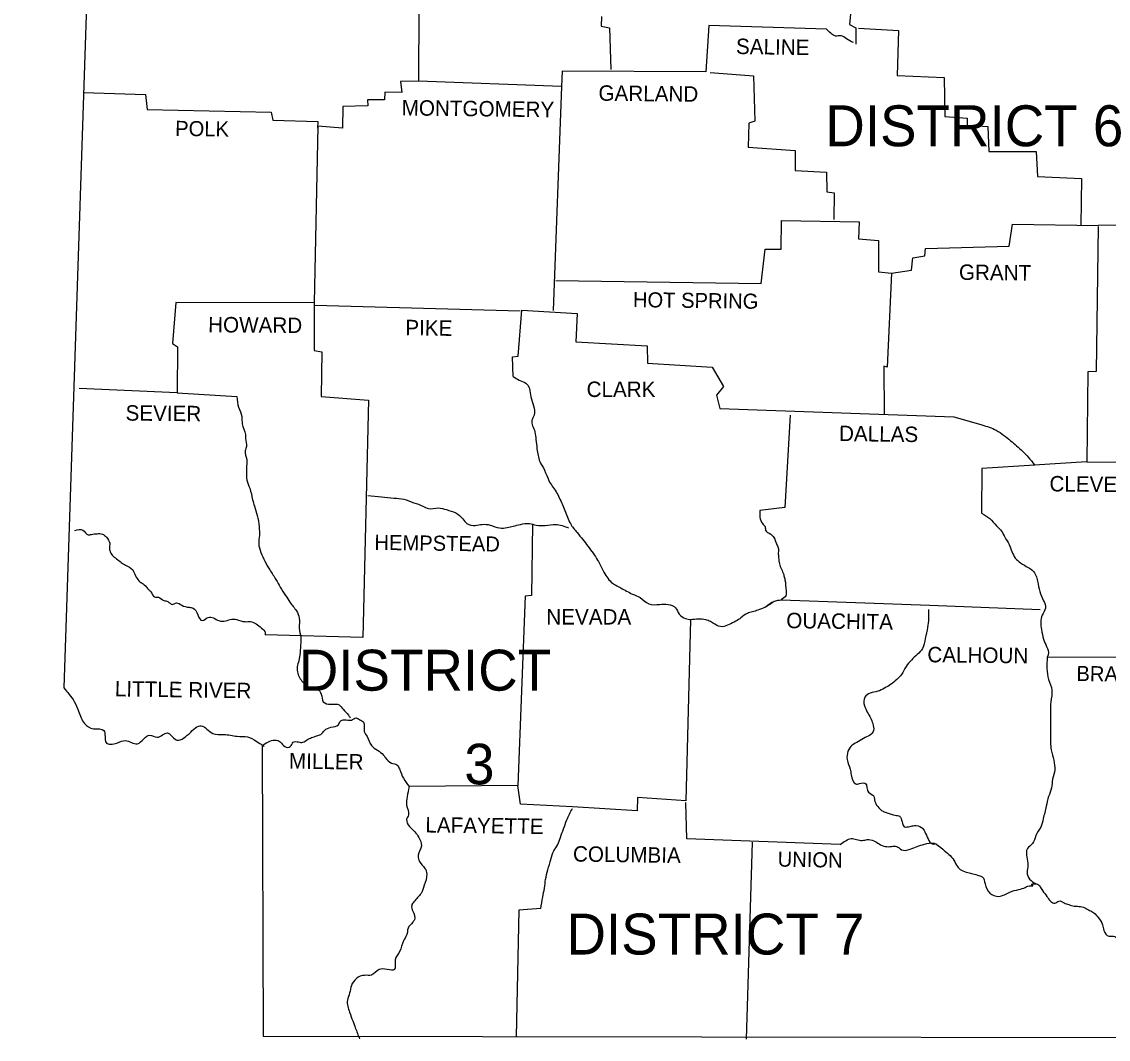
# Model space of a CAD drawing. Extents: x -712 to 3943, y 73 to 2823.
# Drawn here: x 2703.7 to 2999.8, y 1432.6 to 1709.8 of the extents above; entities that cross this region are included whole.
import ezdxf

# ---------------------------------------------------------------- set-up
doc = ezdxf.new("R2010")
doc.units = 0
for name, color, linetype in [('1', 7, 'Continuous'), ('2', 7, 'Continuous'), ('3', 7, 'Continuous')]:
    doc.layers.add(name, color=color, linetype=linetype)

msp = doc.modelspace()

# ---------------------------------------------------------------- linework, layer by layer
at = {"layer": '1'}
for points in [[(2703.71, 1956.42), (2723.96, 1793.81), (2715.15, 1528.37)], [(2811.96, 1733.39), (2811.82, 1693.62), (2806.93, 1693.52), (2807.32, 1690.59), (2802.62, 1690.68), (2802.53, 1688.53), (2797.93, 1688.53), (2798.03, 1686.97), (2791.18, 1686.77), (2791.08, 1680.8), (2784.43, 1681.39), (2783.35, 1633.25), (2745.68, 1633.35), (2744.8, 1622.19), (2746.17, 1621.22), (2746.07, 1608.69), (2719.36, 1609.87)], [(2961.91, 1722.77), (2954.86, 1723.56), (2955.16, 1720.92), (2942.34, 1720.43), (2941.95, 1716.61), (2929.91, 1715.93), (2929.23, 1709.08), (2930.99, 1708.2), (2930.99, 1703.7)], [(2922.97, 1707.81), (2890.97, 1708.78), (2890.09, 1696.16), (2850.96, 1696.36), (2850.76, 1692.15)], [(2861.72, 1711.23), (2861.62, 1708.59), (2863.87, 1708.2), (2864.26, 1696.85)], [(2931.68, 1708.1), (2942.63, 1707.41), (2942.24, 1695.18), (2955.06, 1694.69), (2955.26, 1684.03), (2961.32, 1683.54), (2961.32, 1681.68), (2967, 1681.29), (2967.19, 1674.44), (2980.11, 1674.44), (2980.5, 1667.69), (2992.44, 1667.1), (2992.34, 1654.38)], [(2850.76, 1692.15), (2811.82, 1693.62)], [(2891.27, 1695.97), (2903.11, 1695.09), (2903.5, 1682.76), (2901.83, 1682.17), (2901.64, 1675.62), (2914.46, 1674.74), (2914.46, 1669.35), (2922.97, 1668.86), (2923.07, 1663.48), (2925.12, 1663.19), (2925.02, 1655.95)], [(2720.54, 1690.59), (2737.46, 1690), (2737.85, 1685.89), (2771.71, 1685.2), (2772.1, 1683.05), (2784.43, 1682.66), (2784.33, 1680.8)], [(2850.76, 1692.15), (2848.51, 1631.2)], [(3109.06, 1665.64), (3072.08, 1666.61), (3071.88, 1654.58), (2997.03, 1654.29)], [(2849.2, 1639.32), (2905.16, 1638.53), (2906.24, 1647.83), (2910.64, 1647.83), (2910.74, 1655.66), (2931.87, 1655.36), (2931.68, 1650.67), (2937.16, 1650.27), (2937.16, 1641.66), (2940.68, 1641.37)], [(2940.68, 1641.37), (2946.16, 1642.15), (2946.55, 1645.48), (2949.78, 1646.07), (2949.97, 1648.02), (2972.77, 1648.71), (2973.65, 1654.68), (2997.03, 1654.29)], [(2997.03, 1654.09), (2996.45, 1614.56), (2994.2, 1614.47), (2993.9, 1589.91)], [(2940.68, 1641.37), (2939.5, 1615.74), (2938.62, 1616.03), (2938.72, 1602.72)], [(2783.35, 1633.25), (2783.35, 1620.24), (2785.5, 1619.85), (2785.31, 1607.71), (2798.22, 1606.74), (2796.66, 1542.06), (2770.04, 1542.75)], [(2783.55, 1632.57), (2839.51, 1631.1)], [(2837.65, 1613.19), (2837.46, 1618.57), (2839.02, 1618.67), (2840, 1631.29), (2855.07, 1630.32), (2854.68, 1622.59), (2874.15, 1621.51), (2874.24, 1616.81), (2891.85, 1615.74), (2894.89, 1610.45), (2893.03, 1608.11), (2893.91, 1604.49), (2957.7, 1602.14)], [(2746.07, 1608.69), (2762.31, 1607.71)], [(2913.09, 1602.63), (2911.62, 1577.48), (2904.87, 1576.7)], [(2993.9, 1589.91), (2979.62, 1589.03)], [(2993.9, 1589.91), (3028.54, 1589.71)], [(2979.81, 1589.03), (2965.33, 1588.15), (2965.24, 1575.92)], [(2842.84, 1572.98), (2842.64, 1553.51), (2840.88, 1553.31), (2838.92, 1501.75)], [(2910.64, 1552.34), (2951.15, 1550.87), (2981.18, 1549.69)], [(2885.98, 1546.86), (2884.71, 1497.55), (2871.5, 1498.43), (2871.41, 1494.81), (2853.79, 1495.88)], [(2983.14, 1536.68), (3027.36, 1536.78)], [(2769.26, 1512.61), (2769.46, 1433.46), (3128.04, 1432.87)], [(2853.79, 1495.88), (2839.61, 1496.67), (2838.92, 1501.75), (2809.28, 1501.46)], [(2926.69, 1485.61), (2884.91, 1487.17), (2884.71, 1497.06)], [(2902.72, 1486.29), (2901.15, 1432.58)], [(2845.18, 1468.19), (2839.12, 1467.8), (2838.43, 1433.36)]]:
    msp.add_lwpolyline(points, dxfattribs=at)
for points in [[(2930.31, 1704.19), (2928.45, 1705.16), (2926.98, 1706.04), (2925.41, 1705.95), (2924.14, 1706.73), (2922.97, 1707.81)], [(2837.65, 1613.19), (2839.22, 1612.21), (2841.08, 1611.33), (2842.05, 1609.87), (2842.45, 1607.62), (2843.13, 1605.17), (2843.33, 1602.63), (2842.74, 1601.26), (2843.52, 1598.13), (2843.82, 1595.97), (2844.11, 1593.43), (2844.89, 1590.01), (2846.16, 1587.66), (2847.34, 1584.82), (2849.29, 1581.79), (2850.96, 1578.46), (2851.74, 1576.7), (2853.21, 1573.08), (2855.07, 1570.63), (2858, 1566.91), (2860.64, 1563.1), (2862.11, 1560.26), (2864.36, 1557.13), (2866.91, 1555.57), (2870.13, 1553.9), (2872.19, 1552.92), (2874.54, 1551.26), (2877.57, 1551.06), (2879.82, 1551.06), (2881.88, 1550.18), (2882.85, 1548.42), (2884.61, 1547.25), (2885.98, 1546.86)], [(2762.31, 1607.71), (2762.8, 1604.78), (2763.68, 1602.24), (2763.78, 1600.28), (2764.66, 1597.34), (2764.66, 1596.27), (2764.96, 1594.11), (2764.56, 1592.94), (2765.05, 1590.59), (2764.96, 1588.83), (2764.96, 1587.36), (2765.05, 1584.92), (2765.84, 1582.76), (2766.62, 1579.54), (2767.11, 1577.87), (2767.89, 1575.33), (2768.38, 1572.2), (2768.48, 1569.85), (2768.28, 1567.7), (2768.87, 1565.25), (2769.95, 1562.81), (2771.32, 1560.46), (2772.98, 1557.82), (2774.15, 1555.76), (2775.62, 1553.51), (2776.79, 1551.65), (2778.56, 1549.3), (2779.34, 1547.35), (2779.34, 1544.61), (2779.73, 1542.06), (2779.63, 1539.23), (2779.44, 1536.68), (2778.75, 1533.16), (2779.24, 1531.5), (2781.1, 1529.05), (2782.27, 1528.37), (2784.33, 1527.97), (2785.31, 1526.6), (2785.89, 1524.55), (2787.95, 1523.86), (2790.2, 1523.67), (2791.27, 1522.49), (2792.74, 1520.93), (2793.23, 1520.15)], [(2957.7, 1602.14), (2965.33, 1599.98), (2969.25, 1598.52), (2973.16, 1595.68), (2976.39, 1592.84), (2979.62, 1589.22)], [(2798.03, 1580.71), (2801.74, 1580.42), (2805.17, 1580.03), (2807.81, 1579.73), (2810.55, 1578.75), (2813, 1577.87), (2814.56, 1577.19), (2817.2, 1577.38), (2819.45, 1576.89), (2822, 1576.01), (2823.86, 1574.35), (2825.03, 1573.08), (2827.28, 1572.59), (2829.14, 1572.88), (2831.39, 1572.69), (2833.93, 1571.9), (2835.99, 1572), (2837.65, 1572.39), (2839.61, 1572.88), (2842.05, 1573.08), (2843.91, 1572.69), (2846.36, 1572.59), (2849.2, 1572.88), (2852.72, 1571.9)], [(2904.87, 1576.7), (2904.87, 1574.84), (2905.55, 1573.08), (2906.24, 1572.3), (2906.53, 1571.02), (2907.41, 1570.44), (2908.68, 1569.26), (2909.37, 1567.6), (2909.86, 1566.52), (2909.86, 1565.15), (2909.96, 1563.78), (2910.15, 1562.12), (2911.33, 1559.19), (2911.62, 1558.01), (2911.81, 1557.03), (2911.91, 1555.37), (2911.91, 1553.41), (2910.64, 1552.34)], [(2965.24, 1575.92), (2967.49, 1574.45), (2969.34, 1572.49), (2970.71, 1571.02), (2971.59, 1569.36), (2972.77, 1567.4), (2974.43, 1563.69), (2975.9, 1562.41), (2977.95, 1561.14), (2979.23, 1560.26), (2980.5, 1557.42), (2981.09, 1554.59), (2982.16, 1552.04), (2982.65, 1550.09), (2981.77, 1548.13), (2981.57, 1544.22), (2982.16, 1541.57), (2982.94, 1539.62), (2983.43, 1537.37), (2983.14, 1536.68)], [(2718.19, 1571.22), (2720.34, 1571.32), (2721.81, 1570.05), (2722.69, 1570.14), (2724.25, 1570.34), (2725.72, 1570.24), (2726.8, 1569.36), (2727.68, 1567.8), (2727.58, 1566.33), (2727.68, 1565.74), (2728.36, 1564.47), (2729.54, 1563.49), (2730.81, 1562.51), (2731.98, 1561.73), (2733.94, 1560.46), (2734.14, 1560.07), (2734.92, 1558.5), (2735.9, 1557.23), (2737.07, 1556.45), (2738.34, 1555.08), (2738.93, 1554.49), (2739.91, 1553.12), (2740.98, 1553.02), (2742.45, 1552.14), (2743.53, 1551.85), (2744.7, 1551.06), (2745.88, 1551.46), (2747.34, 1550.87), (2749.3, 1550.28), (2750.38, 1550.09), (2751.65, 1548.23), (2752.92, 1546.66), (2754.49, 1547.54), (2757.42, 1546.66), (2759.28, 1546.56), (2760.94, 1547.05), (2762.22, 1546.96), (2764.56, 1546.37), (2766.03, 1546.37), (2767.6, 1545.78), (2769.06, 1544.61), (2770.04, 1543.34), (2770.04, 1542.75)], [(2908.78, 1551.95), (2906.24, 1550.28), (2904.28, 1549.5), (2902.81, 1549.01), (2901.44, 1548.62), (2899.68, 1547.44), (2898.31, 1546.47), (2896.45, 1545.59), (2894.69, 1545), (2892.54, 1545.68), (2891.37, 1546.37), (2890.09, 1546.86), (2885.98, 1546.86)], [(2906.24, 1550.28), (2908.78, 1551.95), (2910.64, 1552.34)], [(2950.75, 1549.69), (2950.56, 1544.8), (2949.87, 1541.77), (2949.19, 1539.03), (2947.72, 1537.46), (2946.16, 1535.9), (2944.69, 1534.14), (2943.42, 1531.99), (2942.14, 1530.62), (2940.48, 1529.25), (2938.82, 1528.27), (2936.96, 1527.39), (2934.9, 1526.9), (2933.44, 1525.82), (2933.34, 1523.47), (2935, 1520.15), (2935.59, 1518.58), (2935.79, 1516.72), (2935.1, 1515.65), (2933.53, 1514.77), (2931.68, 1513.69), (2930.01, 1512.71), (2928.84, 1511.05), (2928.64, 1508.8), (2929.43, 1506.16), (2929.72, 1504.59), (2930.99, 1502.14), (2931.97, 1502.24), (2933.73, 1502.14), (2933.93, 1501.65), (2934.02, 1501.17), (2934.42, 1499.89), (2935.88, 1498.82), (2936.08, 1497.84), (2936.96, 1495.98), (2938.43, 1494.71), (2939.5, 1494.32), (2941.75, 1493.63), (2942.93, 1493.34), (2944.2, 1490.5), (2945.77, 1490.6), (2946.94, 1490.79), (2948.9, 1490.31), (2949.78, 1489.13), (2950.66, 1487.17), (2951.83, 1485.8), (2952.61, 1485.8)], [(2983.14, 1536.68), (2983.53, 1530.62), (2984.41, 1527.68), (2984.12, 1524.55), (2984.02, 1521.52), (2984.02, 1518.78), (2984.02, 1516.14), (2984.02, 1513.4), (2984.22, 1511.44), (2984.9, 1508.6), (2985.19, 1505.96), (2984.61, 1503.42), (2984.31, 1501.07), (2983.53, 1498.72), (2982.85, 1496.08), (2982.06, 1492.65), (2981.38, 1490.4), (2980.01, 1488.06), (2979.13, 1485.9), (2977.76, 1484.53), (2977.56, 1482.18), (2977.86, 1480.03), (2977.66, 1478.08), (2978.35, 1476.22), (2980.11, 1474.94)], [(2715.15, 1528.37), (2717.99, 1524.65), (2719.17, 1522.01), (2720.83, 1518.58), (2723.28, 1517.21), (2726.11, 1516.72), (2726.7, 1513.4), (2729.63, 1513.3), (2731.98, 1513.98), (2735.21, 1513.1), (2738.64, 1515.45), (2740.59, 1514.86), (2743.43, 1516.04), (2745.58, 1514.28), (2749.3, 1515.84), (2752.63, 1517.99), (2755.76, 1515.94), (2758.79, 1515.65), (2762.41, 1515.16), (2765.25, 1514.96), (2767.79, 1513.69), (2769.65, 1512.42), (2769.26, 1512.61)], [(2769.26, 1512.61), (2772.68, 1514.08), (2774.15, 1513.59), (2775.42, 1512.32), (2776.89, 1512.32), (2777.67, 1513.49), (2779.14, 1513.59), (2780.32, 1513.49), (2781.59, 1514.28), (2782.66, 1514.77), (2784.13, 1515.25), (2785.21, 1515.65), (2786.19, 1516.72), (2787.95, 1517.6), (2790, 1518.29), (2790.59, 1519.27), (2791.57, 1519.66), (2793.52, 1519.56), (2794.8, 1520.15), (2795.87, 1519.66), (2796.85, 1518.97), (2797.05, 1516.43), (2797.83, 1515.06), (2799, 1512.61), (2800.67, 1511.34), (2802.23, 1510.07), (2802.82, 1509.29), (2804.48, 1507.82), (2805.95, 1507.33), (2806.64, 1506.25), (2807.71, 1503.71), (2809.28, 1501.46)], [(2809.28, 1501.46), (2808.69, 1498.62), (2808.59, 1496.37), (2809.08, 1493.73), (2808.59, 1492.46), (2809.38, 1490.6), (2810.84, 1489.13), (2811.92, 1487.57), (2812.6, 1485.32), (2811.72, 1482.77), (2812.7, 1480.13), (2813.58, 1479.15), (2814.07, 1477.59), (2813.39, 1474.55), (2812.51, 1472.3), (2810.55, 1470.05), (2809.96, 1468.98), (2810.26, 1467.51), (2810.74, 1465.16), (2810.26, 1464.48), (2808.98, 1462.81), (2808.59, 1460.95), (2807.71, 1459.39), (2806.73, 1456.55), (2805.46, 1454.2), (2805.27, 1451.56), (2803.31, 1451.56), (2801.06, 1451.56), (2799, 1450.09), (2797.15, 1450), (2794.89, 1449.11), (2793.52, 1447.26), (2793.04, 1445.2), (2792.45, 1443.24), (2793.04, 1439.92), (2793.92, 1437.57), (2794.6, 1435.71), (2795.78, 1432.68)], [(2845.18, 1468.19), (2845.67, 1471.32), (2846.16, 1473.77), (2846.46, 1476.12), (2847.04, 1478.76), (2847.92, 1481.6), (2848.71, 1483.95), (2849.78, 1485.61), (2850.47, 1487.57), (2851.35, 1489.91), (2852.23, 1492.36), (2853.79, 1495.49)], [(2926.69, 1485.61), (2928.25, 1486.69), (2929.72, 1487.27), (2931.19, 1486.98), (2932.75, 1486.78), (2934.12, 1486.98), (2935.88, 1486.69), (2937.35, 1485.8), (2939.01, 1485.12), (2940.68, 1485.12), (2942.14, 1485.12), (2943.42, 1484.24), (2945.77, 1484.34), (2947.72, 1485.12), (2949.68, 1485.71), (2952.32, 1486), (2954.67, 1484.34), (2956.33, 1482.97), (2957.7, 1481.4), (2958.68, 1479.64), (2959.76, 1478.66), (2961.52, 1477.98), (2962.89, 1477.68), (2964.55, 1477.19), (2965.43, 1476.8), (2966.21, 1474.94), (2967.49, 1472.4), (2969.93, 1471.52), (2972.96, 1472.69), (2975.41, 1473.38), (2977.17, 1473.97), (2978.25, 1474.36), (2979.23, 1474.46), (2978.93, 1474.65), (2980.11, 1474.94), (2981.18, 1474.16), (2981.87, 1473.09), (2983.04, 1471.52), (2984.12, 1470.15), (2985.19, 1469.66), (2986.27, 1470.25), (2987.74, 1469.76), (2989.01, 1469.27), (2990.48, 1468.88), (2991.75, 1468.78), (2993.41, 1468.39), (2994.69, 1467.7), (2995.86, 1467.02), (2997.03, 1465.75), (2998.21, 1463.79), (2998.6, 1462.23), (2999.97, 1460.66), (3001.24, 1460.66), (3003.1, 1458.12), (3003.78, 1457.14), (3005.25, 1455.38), (3006.33, 1455.38), (3008.38, 1454.98)]]:
    msp.add_spline(points, degree=3, dxfattribs=at)

# ---------------------------------------------------------------- texts
at = {"layer": '2'}
for s, height, rotation, p in [('SALINE', 4.207, 359.1491, (2898.31, 1701.05)), ('GARLAND', 4.207, 359.3658, (2860.84, 1688.33)), ('MONTGOMERY', 4.207, 359.2944, (2807.22, 1684.32)), ('POLK', 4.108, 359.2152, (2745.49, 1678.75)), ('GRANT', 4.207, 359.4032, (2959.07, 1639.51)), ('HOT SPRING', 4.109, 359.2216, (2870.23, 1632.08)), ('HOWARD', 4.207, 359.5145, (2754.49, 1625.23)), ('PIKE', 4.206, 359.0452, (2808.2, 1624.44)), ('SEVIER', 4.207, 359.4271, (2731.98, 1601.16)), ('DALLAS', 4.206, 359.2462, (2926.39, 1595.58)), ('CLEVELAND', 4.207, 359.3377, (2983.73, 1581.88)), ('HEMPSTEAD', 4.108, 359.1885, (2799.79, 1565.94)), ('OUACHITA', 4.207, 359.2043, (2912.01, 1544.61)), ('CALHOUN', 4.207, 359.3634, (2950.46, 1535.31)), ('BRADLEY', 4.108, 359.1449, (2991.07, 1530.22)), ('LITTLE RIVER', 4.2073, 359.1697, (2729.05, 1526.02)), ('MILLER', 4.206, 359.1319, (2776.5, 1506.35)), ('LAFAYETTE', 4.206, 359.1839, (2813.68, 1488.94)), ('COLUMBIA', 4.206, 359.2125, (2853.89, 1481.01)), ('UNION', 4.109, 358.9584, (2909.66, 1479.64))]:
    msp.add_text(s, height=height, rotation=rotation, dxfattribs=at).set_placement(p)
for s, p in [('CLARK', (2857.63, 1607.59)), ('NEVADA', (2846.65, 1545.59))]:
    msp.add_text(s, height=4.207, dxfattribs=at).set_placement(p)
at = {"layer": '3'}
for s, height, p in [('DISTRICT 6', 11.154, (2922.67, 1675.91)), ('DISTRICT', 11.154, (2779.19, 1527.57)), ('3', 11.06, (2824.3, 1502.04)), ('DISTRICT 7', 11.154, (2852.13, 1455.67))]:
    msp.add_text(s, height=height, dxfattribs=at).set_placement(p)

doc.saveas('drawing.dxf')
